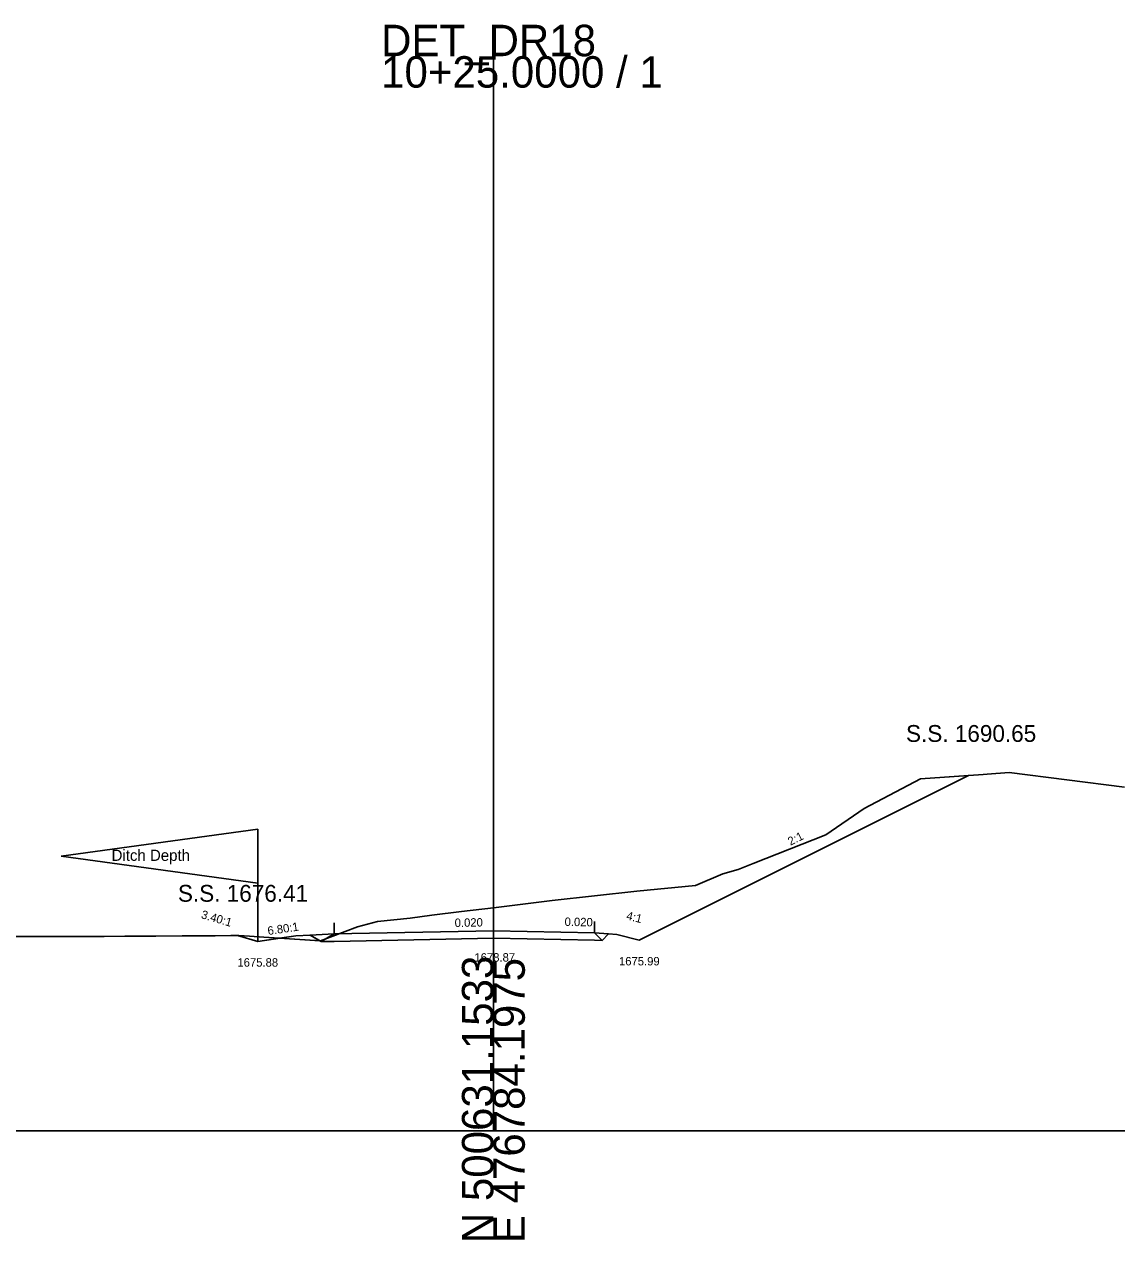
# Model space of a CAD drawing. Extents: x -26 to 303, y -10 to 3627.
# Drawn here: x 108.2 to 205.5, y 490.3 to 598.6 of the extents above; entities that cross this region are included whole.
import ezdxf

# ---------------------------------------------------------------- set-up
doc = ezdxf.new("R2010")
doc.units = 0
for name, color, linetype in [('Exist Cross Section Cell', 7, 'Continuous'), ('Exist XS Center Line Elevation Label', 7, 'Continuous'), ('Exist XS Ground Line', 7, 'Continuous'), ('Prop XS Ditch Slope Text', 7, 'Continuous'), ('Prop XS Ditch Standard Text', 7, 'Continuous'), ('Prop XS Dump Level', 7, 'Continuous'), ('Prop XS Earthwork Shape', 7, 'Continuous'), ('Prop XS EOT Tick Mark', 7, 'Continuous'), ('Prop XS Finish Grade', 7, 'Continuous'), ('Prop XS Finish Grade Earthwork', 7, 'Continuous'), ('Prop XS Finish Grade Pavement', 7, 'Continuous'), ('Prop XS Hydro Typical Ditch Data', 7, 'Continuous'), ('Prop XS Pvmt Edge Slope', 7, 'Continuous'), ('Prop XS SE Text', 7, 'Continuous'), ('Prop XS Shoulder Borrow Shape', 7, 'Continuous'), ('Prop XS Side Slope Text', 7, 'Continuous'), ('Prop XS SS Elevation Text', 7, 'Continuous'), ('Prop XS Subgrade Earthwork', 7, 'Continuous')]:
    doc.layers.add(name, color=color, linetype=linetype)

msp = doc.modelspace()

# ---------------------------------------------------------------- linework, layer by layer
at = {"layer": 'Exist Cross Section Cell'}
for p, q in [((150, 500), (150, 595.73)), ((0, 500), (150, 500)), ((150, 500), (300, 500))]:
    msp.add_line(p, q, dxfattribs=at)
at = {"layer": 'Exist XS Ground Line'}
msp.add_lwpolyline([(107.13, 517.31), (109.49, 517.31), (110.26, 517.31), (112.08, 517.31), (113.6, 517.32), (114.64, 517.32), (115.34, 517.32), (117.17, 517.33), (118.84, 517.34), (119.94, 517.35), (122.28, 517.36), (122.75, 517.36), (123.92, 517.37), (124.77, 517.38), (125.22, 517.38), (126.61, 517.4), (127.33, 517.41), (128.27, 517.35), (129.55, 517.26), (134.59, 516.92), (137.9, 518.18), (139.69, 518.66), (142.6, 518.94), (144.51, 519.22), (147.17, 519.53), (150, 519.87), (155.24, 520.51), (162.79, 521.34), (168.01, 521.85), (170.44, 522.9), (171.82, 523.28), (173.13, 523.82), (179.63, 526.38), (183.02, 528.73), (188.04, 531.36), (193.64, 531.74), (194, 531.78), (195.94, 531.91), (206.22, 530.61)], dxfattribs=at)
at = {"layer": 'Prop XS Dump Level'}
for p, q in [((129.01, 526.88), (111.5, 524.48)), ((129.01, 522.08), (129.01, 526.88)), ((111.5, 524.48), (129.01, 522.08)), ((129.01, 516.88), (129.01, 522.08)), ((150, 517.83), (135.81, 517.54)), ((159, 517.65), (150, 517.83))]:
    msp.add_line(p, q, dxfattribs=at)
at = {"layer": 'Prop XS Earthwork Shape'}
for points in [[(134.65, 516.86), (134.54, 516.93), (134.59, 516.92), (137.9, 518.18), (139.69, 518.66), (142.6, 518.94), (144.51, 519.22), (147.17, 519.53), (150, 519.87), (155.24, 520.51), (162.79, 521.34), (168.01, 521.85), (170.44, 522.9), (171.82, 523.28), (173.13, 523.82), (179.63, 526.38), (183.02, 528.73), (188.04, 531.36), (192.33, 531.65), (163, 516.99), (161, 517.49), (160.26, 517.55), (159.68, 516.97), (159, 516.98), (150, 517.16), (135.81, 516.88)], [(129.01, 516.88), (127.22, 517.41), (127.33, 517.41), (128.27, 517.35), (129.55, 517.26), (130.96, 517.17)], [(132.41, 517.38), (130.96, 517.17), (134.54, 516.93), (133.67, 517.44)]]:
    msp.add_lwpolyline(points, close=True, dxfattribs=at)
at = {"layer": 'Prop XS EOT Tick Mark'}
for p, q in [((159, 517.65), (159, 518.65)), ((135.81, 517.54), (135.81, 518.54))]:
    msp.add_line(p, q, dxfattribs=at)
at = {"layer": 'Prop XS Finish Grade'}
for p, q in [((135.81, 517.54), (133.67, 517.44)), ((159, 517.65), (160.26, 517.55))]:
    msp.add_line(p, q, dxfattribs=at)
at = {"layer": 'Prop XS Finish Grade Earthwork'}
for p, q in [((163, 516.99), (192.33, 531.65)), ((160.26, 517.55), (161, 517.49)), ((129.01, 516.88), (127.22, 517.41)), ((132.41, 517.38), (129.01, 516.88)), ((133.67, 517.44), (132.41, 517.38)), ((161, 517.49), (163, 516.99))]:
    msp.add_line(p, q, dxfattribs=at)
at = {"layer": 'Prop XS Finish Grade Pavement'}
for p, q in [((135.81, 517.54), (150, 517.83)), ((150, 517.83), (159, 517.65))]:
    msp.add_line(p, q, dxfattribs=at)
at = {"layer": 'Prop XS Hydro Typical Ditch Data'}
for p, q in [((163, 516.99), (192.33, 531.65)), ((129.01, 516.88), (127.22, 517.41)), ((132.41, 517.38), (129.01, 516.88)), ((161, 517.49), (163, 516.99))]:
    msp.add_line(p, q, dxfattribs=at)
at = {"layer": 'Prop XS Pvmt Edge Slope'}
for p, q in [((135.81, 517.54), (134.65, 516.86)), ((159, 517.65), (159.68, 516.97))]:
    msp.add_line(p, q, dxfattribs=at)
at = {"layer": 'Prop XS Shoulder Borrow Shape'}
for points in [[(135.81, 517.54), (134.65, 516.86), (133.67, 517.44)], [(135.81, 517.54), (134.65, 516.86), (133.67, 517.44)], [(159.68, 516.97), (160.26, 517.55), (159, 517.65)], [(159.68, 516.97), (160.26, 517.55), (159, 517.65)]]:
    msp.add_lwpolyline(points, close=True, dxfattribs=at)
at = {"layer": 'Prop XS Subgrade Earthwork'}
for p, q in [((159.68, 516.97), (160.26, 517.55)), ((134.65, 516.86), (133.67, 517.44)), ((135.81, 516.88), (134.65, 516.86)), ((150, 517.16), (135.81, 516.88)), ((159, 516.98), (150, 517.16)), ((159, 516.98), (159.68, 516.97))]:
    msp.add_line(p, q, dxfattribs=at)

# ---------------------------------------------------------------- texts
at = {"layer": 'Exist Cross Section Cell'}
for s, p in [('DET_DR18', (140, 595.73)), ('10+25.0000 / 1', (140, 592.93))]:
    msp.add_text(s, height=2.8, dxfattribs=at).set_placement(p)
for s, p in [('N 500631.1533', (150, 490)), ('E 476784.1975', (152.8, 490))]:
    msp.add_text(s, height=2.8, rotation=90, dxfattribs=at).set_placement(p)
at = {"layer": 'Exist XS Center Line Elevation Label'}
msp.add_text('1678.87', height=0.75, dxfattribs=at).set_placement((148.31, 515.08))
at = {"layer": 'Prop XS Ditch Slope Text'}
for s, rotation, p in [('4:1', 345.9638, (161.79, 518.84)), ('6.80:1', 8.3662, (129.94, 517.44))]:
    msp.add_text(s, height=0.75, rotation=rotation, dxfattribs=at).set_placement(p)
at = {"layer": 'Prop XS Ditch Standard Text'}
for s, p in [('1675.88', (127.2, 514.63)), ('1675.99', (161.19, 514.74))]:
    msp.add_text(s, height=0.75, dxfattribs=at).set_placement(p)
at = {"layer": 'Prop XS Dump Level'}
for s, height, p in [('Ditch Depth', 1, (115.99, 524.05)), ('Case1', 0.04, (132.41, 517.34)), ('Case1', 0.04, (161, 517.45))]:
    msp.add_text(s, height=height, dxfattribs=at).set_placement(p)
at = {"layer": 'Prop XS SE Text'}
for rotation, p in [(1.1458, (146.56, 518.16)), (358.8542, (156.34, 518.26))]:
    msp.add_text('0.020', height=0.75, rotation=rotation, dxfattribs=at).set_placement(p)
at = {"layer": 'Prop XS Side Slope Text'}
for s, rotation, p in [('2:1', 26.5651, (176.46, 525.39)), ('3.40:1', 343.6098, (123.91, 518.96))]:
    msp.add_text(s, height=0.75, rotation=rotation, dxfattribs=at).set_placement(p)
at = {"layer": 'Prop XS SS Elevation Text'}
for s, p in [('S.S. 1690.65', (186.76, 534.65)), ('S.S. 1676.41', (121.9, 520.41))]:
    msp.add_text(s, height=1.5, dxfattribs=at).set_placement(p)

doc.saveas('drawing.dxf')
